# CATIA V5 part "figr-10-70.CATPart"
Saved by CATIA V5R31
Part number: Part1
Bounding box of the stored display mesh (mm): x -80.563 to 63.541, y -72 to 69, z -55 to 56
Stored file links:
  D:\PROJECTS\Project 2021\US EDITION\CATIA V5 6R 2021\Resources\Part Files\c10_catia_v5_6r2021_prt\c10_catia_v5_6r2021_prt\figr-10-70.CATPart
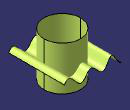
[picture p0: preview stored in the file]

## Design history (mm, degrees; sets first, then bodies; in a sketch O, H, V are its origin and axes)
Set1
  Sketch1 on xy-plane, origin (0, 0, 0), H (-1, 0, 0), V (0, -1, 0)
    circle A1 centre (0, 0) radius 45.985
  Extrude1: Element1 Sketch1, Lim1 56, Lim2 55, Direction xy-plane
  Sketch2 on zx-plane, origin (0, 0, 0), H (1, 0, 0), V (0, 0, -1)
    spline S1 through (-80.5635, 24.8913) (-73.6025, 19.8803) (-54.8525, -3.3629) (-35.1982, 19.8803) (-2.6271, -1.6506) (16.6996, 17.2854) (52.4104, -6.7877) (63.5409, 1.5862)
  Extrude2: Element1 Sketch2, Lim1 72, Lim2 69, Direction Sketch1.V
Body1 (main body)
